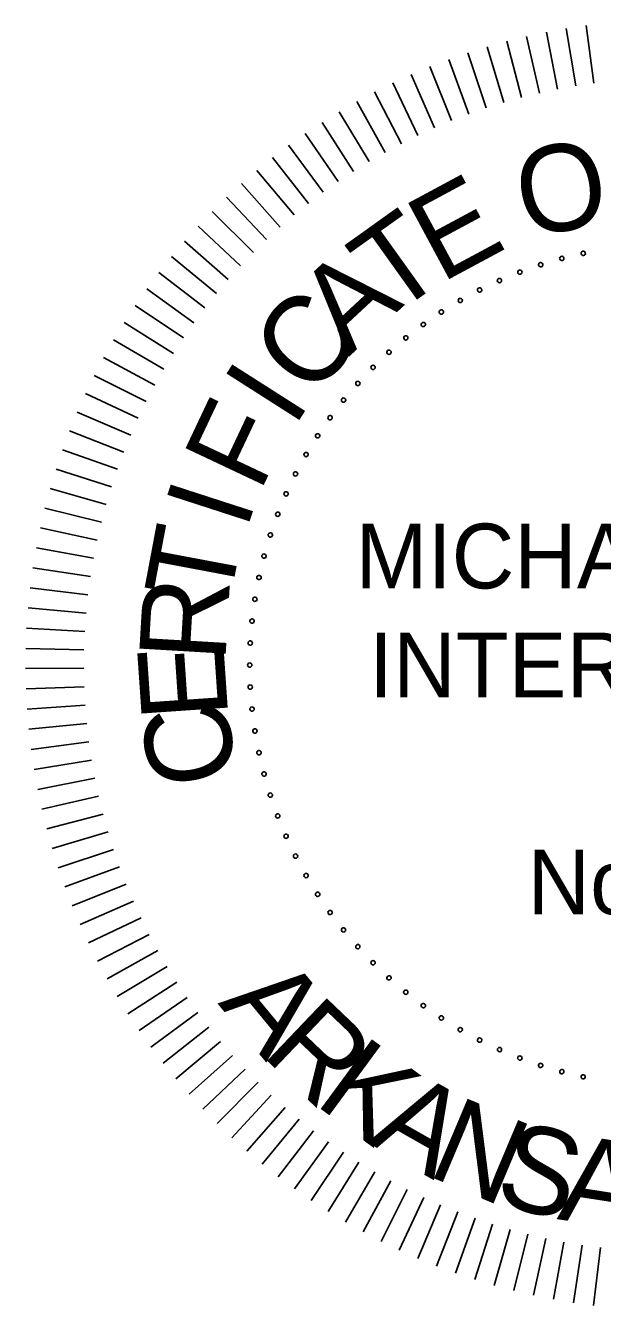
# Model space of a CAD drawing. Extents: x 166 to 3426, y 71 to 2074.
# Drawn here: x 2685.7 to 2797, y 232.1 to 479 of the extents above; entities that cross this region are included whole.
import ezdxf

# ---------------------------------------------------------------- set-up
doc = ezdxf.new("R2010")
doc.units = 0
doc.layers.add('G-ANNO-TEXT', color=7, linetype='Continuous')

msp = doc.modelspace()

# ---------------------------------------------------------------- linework, layer by layer
at = {"layer": 'G-ANNO-TEXT'}
for points in [[(2784.87, 465.99), (2782.36, 476.93)], [(2782.36, 476.93), (2784.87, 465.99)], [(2788.35, 466.73), (2786.19, 477.74)], [(2786.19, 477.74), (2788.35, 466.73)], [(2791.85, 467.36), (2790.03, 478.44)], [(2790.03, 478.44), (2791.85, 467.36)], [(2795.37, 467.88), (2793.9, 479.01)], [(2793.9, 479.01), (2795.37, 467.88)], [(2777.99, 464.19), (2774.8, 474.94)], [(2774.8, 474.94), (2777.99, 464.19)], [(2781.42, 465.14), (2778.57, 476)], [(2778.57, 476), (2781.42, 465.14)], [(2771.24, 461.95), (2767.38, 472.49)], [(2767.38, 472.49), (2771.24, 461.95)], [(2774.6, 463.12), (2771.07, 473.77)], [(2771.07, 473.77), (2774.6, 463.12)], [(2764.64, 459.29), (2760.13, 469.57)], [(2760.13, 469.57), (2764.64, 459.29)], [(2767.92, 460.67), (2763.73, 471.09)], [(2763.73, 471.09), (2767.92, 460.67)], [(2761.41, 457.81), (2756.57, 467.94)], [(2756.57, 467.94), (2761.41, 457.81)], [(2755.09, 454.55), (2749.63, 464.35)], [(2749.63, 464.35), (2755.09, 454.55)], [(2758.22, 456.23), (2753.07, 466.2)], [(2753.07, 466.2), (2758.22, 456.23)], [(2752.01, 452.77), (2746.24, 462.4)], [(2746.24, 462.4), (2752.01, 452.77)], [(2748.99, 450.89), (2742.92, 460.34)], [(2742.92, 460.34), (2748.99, 450.89)], [(2746.03, 448.92), (2739.67, 458.17)], [(2739.67, 458.17), (2746.03, 448.92)], [(2743.13, 446.86), (2736.48, 455.91)], [(2740.3, 444.71), (2733.37, 453.54)], [(2733.37, 453.54), (2740.3, 444.71)], [(2737.53, 442.47), (2730.33, 451.08)], [(2730.33, 451.08), (2737.53, 442.47)], [(2734.84, 440.15), (2727.37, 448.52)], [(2727.37, 448.52), (2734.84, 440.15)], [(2732.22, 437.74), (2724.5, 445.88)], [(2724.5, 445.88), (2732.22, 437.74)], [(2729.68, 435.25), (2721.7, 443.14)], [(2721.7, 443.14), (2729.68, 435.25)], [(2727.22, 432.68), (2719, 440.32)], [(2719, 440.32), (2727.22, 432.68)], [(2724.84, 430.04), (2716.38, 437.41)], [(2716.38, 437.41), (2724.84, 430.04)], [(2722.55, 427.32), (2713.86, 434.43)], [(2713.86, 434.43), (2722.55, 427.32)], [(2720.34, 424.53), (2711.43, 431.36)], [(2711.43, 431.36), (2720.34, 424.53)], [(2718.22, 421.68), (2709.1, 428.22)], [(2709.1, 428.22), (2718.22, 421.68)], [(2716.19, 418.76), (2706.87, 425.01)], [(2706.87, 425.01), (2716.19, 418.76)], [(2714.26, 415.77), (2704.75, 421.73)], [(2704.75, 421.73), (2714.26, 415.77)], [(2712.41, 412.73), (2702.72, 418.39)], [(2702.72, 418.39), (2712.41, 412.73)], [(2710.67, 409.63), (2700.8, 414.98)], [(2700.8, 414.98), (2710.67, 409.63)], [(2709.02, 406.48), (2698.99, 411.52)], [(2698.99, 411.52), (2709.02, 406.48)], [(2707.48, 403.27), (2697.29, 408)], [(2697.29, 408), (2707.48, 403.27)], [(2706.03, 400.02), (2695.71, 404.42)], [(2695.71, 404.42), (2706.03, 400.02)], [(2704.69, 396.73), (2694.23, 400.8)], [(2694.23, 400.8), (2704.69, 396.73)], [(2703.45, 393.4), (2692.87, 397.14)], [(2692.87, 397.14), (2703.45, 393.4)], [(2702.32, 390.03), (2691.62, 393.43)], [(2691.62, 393.43), (2702.32, 390.03)], [(2701.29, 386.62), (2690.49, 389.69)], [(2690.49, 389.69), (2701.29, 386.62)], [(2700.37, 383.18), (2689.48, 385.91)], [(2689.48, 385.91), (2700.37, 383.18)], [(2699.56, 379.72), (2688.59, 382.11)], [(2688.59, 382.11), (2699.56, 379.72)], [(2698.86, 376.23), (2687.82, 378.28)], [(2687.82, 378.28), (2698.86, 376.23)], [(2698.26, 372.73), (2687.17, 374.42)], [(2687.17, 374.42), (2698.26, 372.73)], [(2697.78, 369.2), (2686.64, 370.55)], [(2686.64, 370.55), (2697.78, 369.2)], [(2697.41, 365.67), (2686.23, 366.66)], [(2686.23, 366.66), (2697.41, 365.67)], [(2697.15, 362.12), (2685.95, 362.76)], [(2685.95, 362.76), (2697.15, 362.12)], [(2697, 358.57), (2685.79, 358.86)], [(2685.79, 358.86), (2697, 358.57)], [(2696.97, 355.01), (2685.75, 354.95)], [(2685.75, 354.95), (2696.97, 355.01)], [(2697.04, 351.45), (2685.83, 351.04)], [(2685.83, 351.04), (2697.04, 351.45)], [(2697.23, 347.9), (2686.04, 347.13)], [(2686.04, 347.13), (2697.23, 347.9)], [(2697.53, 344.36), (2686.36, 343.24)], [(2686.36, 343.24), (2697.53, 344.36)], [(2697.94, 340.82), (2686.81, 339.36)], [(2686.81, 339.36), (2697.94, 340.82)], [(2698.46, 337.31), (2687.39, 335.49)], [(2687.39, 335.49), (2698.46, 337.31)], [(2699.09, 333.81), (2688.08, 331.64)], [(2688.08, 331.64), (2699.09, 333.81)], [(2699.83, 330.33), (2688.89, 327.82)], [(2688.89, 327.82), (2699.83, 330.33)], [(2700.68, 326.87), (2689.83, 324.02)], [(2689.83, 324.02), (2700.68, 326.87)], [(2701.64, 323.45), (2690.88, 320.26)], [(2690.88, 320.26), (2701.64, 323.45)], [(2702.71, 320.05), (2692.05, 316.53)], [(2692.05, 316.53), (2702.71, 320.05)], [(2703.88, 316.7), (2693.34, 312.83)], [(2693.34, 312.83), (2703.88, 316.7)], [(2705.15, 313.38), (2694.74, 309.19)], [(2694.74, 309.19), (2705.15, 313.38)], [(2706.53, 310.1), (2696.26, 305.58)], [(2696.26, 305.58), (2706.53, 310.1)], [(2708.01, 306.86), (2697.88, 302.03)], [(2697.88, 302.03), (2708.01, 306.86)], [(2709.6, 303.68), (2699.62, 298.53)], [(2699.62, 298.53), (2709.6, 303.68)], [(2711.28, 300.54), (2701.47, 295.08)], [(2701.47, 295.08), (2711.28, 300.54)], [(2713.06, 297.46), (2703.43, 291.7)], [(2703.43, 291.7), (2713.06, 297.46)], [(2714.93, 294.44), (2705.49, 288.38)], [(2705.49, 288.38), (2714.93, 294.44)], [(2716.9, 291.48), (2707.65, 285.12)], [(2707.65, 285.12), (2716.9, 291.48)], [(2718.96, 288.58), (2709.92, 281.94)], [(2709.92, 281.94), (2718.96, 288.58)], [(2721.11, 285.75), (2712.28, 278.82)], [(2712.28, 278.82), (2721.11, 285.75)], [(2723.35, 282.99), (2714.75, 275.78)], [(2714.75, 275.78), (2723.35, 282.99)], [(2725.68, 280.29), (2717.3, 272.83)], [(2717.3, 272.83), (2725.68, 280.29)], [(2728.09, 277.68), (2719.95, 269.95)], [(2719.95, 269.95), (2728.09, 277.68)], [(2730.58, 275.14), (2722.68, 267.16)], [(2722.68, 267.16), (2730.58, 275.14)], [(2733.14, 272.68), (2725.51, 264.45)], [(2725.51, 264.45), (2733.14, 272.68)], [(2728.41, 261.84), (2735.79, 270.3)], [(2735.79, 270.3), (2728.41, 261.84)], [(2731.4, 259.32), (2738.5, 268)], [(2738.5, 268), (2731.4, 259.32)], [(2734.46, 256.89), (2741.29, 265.79)], [(2741.29, 265.79), (2734.46, 256.89)], [(2737.6, 254.56), (2744.15, 263.67)], [(2744.15, 263.67), (2737.6, 254.56)], [(2740.81, 252.33), (2747.07, 261.65)], [(2747.07, 261.65), (2740.81, 252.33)], [(2744.09, 250.2), (2750.05, 259.71)], [(2750.05, 259.71), (2744.09, 250.2)], [(2747.44, 248.18), (2753.1, 257.87)], [(2753.1, 257.87), (2747.44, 248.18)], [(2750.84, 246.26), (2756.2, 256.12)], [(2756.2, 256.12), (2750.84, 246.26)], [(2754.31, 244.45), (2759.35, 254.48)], [(2759.35, 254.48), (2754.31, 244.45)], [(2757.83, 242.75), (2762.55, 252.93)], [(2762.55, 252.93), (2757.83, 242.75)], [(2761.4, 241.16), (2765.8, 251.48)], [(2765.8, 251.48), (2761.4, 241.16)], [(2765.02, 239.68), (2769.09, 250.14)], [(2769.09, 250.14), (2765.02, 239.68)], [(2768.69, 238.32), (2772.43, 248.9)], [(2772.43, 248.9), (2768.69, 238.32)], [(2772.39, 237.08), (2775.8, 247.77)], [(2775.8, 247.77), (2772.39, 237.08)], [(2776.13, 235.95), (2779.21, 246.74)], [(2779.21, 246.74), (2776.13, 235.95)], [(2779.91, 234.94), (2782.64, 245.82)], [(2782.64, 245.82), (2779.91, 234.94)], [(2783.72, 234.05), (2786.1, 245.01)], [(2786.1, 245.01), (2783.72, 234.05)], [(2787.55, 233.27), (2789.59, 244.31)], [(2789.59, 244.31), (2787.55, 233.27)], [(2791.4, 232.62), (2793.1, 243.72)], [(2793.1, 243.72), (2791.4, 232.62)], [(2795.28, 232.09), (2796.62, 243.24)], [(2796.62, 243.24), (2795.28, 232.09)]]:
    msp.add_lwpolyline(points, dxfattribs=at)
for centre, start, end in [((2793.3, 435.08), 12, 192), ((2793.3, 435.08), 192, 12), ((2785.09, 432.88), 18, 198), ((2785.09, 432.88), 198, 18), ((2789.17, 434.09), 15, 195), ((2789.17, 434.09), 195, 15), ((2777.15, 429.83), 24, 204), ((2777.15, 429.83), 204, 24), ((2781.08, 431.46), 21, 201), ((2781.08, 431.46), 201, 21), ((2773.32, 428), 27, 207), ((2773.32, 428), 207, 27), ((2769.58, 425.97), 30, 210), ((2769.58, 425.97), 210, 30), ((2765.95, 423.75), 33, 213), ((2765.95, 423.75), 213, 33), ((2762.45, 421.34), 36, 216), ((2762.45, 421.34), 216, 36), ((2759.08, 418.76), 39, 219), ((2759.08, 418.76), 219, 39), ((2755.84, 415.99), 42, 222), ((2755.84, 415.99), 222, 42), ((2752.76, 413.07), 45, 225), ((2752.76, 413.07), 225, 45), ((2749.83, 409.98), 48, 228), ((2749.83, 409.98), 228, 48), ((2747.07, 406.75), 51, 231), ((2747.07, 406.75), 231, 51), ((2744.48, 403.38), 54, 234), ((2744.48, 403.38), 234, 54), ((2742.07, 399.87), 57, 237), ((2742.07, 399.87), 237, 57), ((2739.85, 396.25), 60, 240), ((2739.85, 396.25), 240, 60), ((2737.82, 392.51), 63, 243), ((2737.82, 392.51), 243, 63), ((2735.99, 388.67), 66, 246), ((2735.99, 388.67), 246, 66), ((2734.37, 384.74), 69, 249), ((2734.37, 384.74), 249, 69), ((2732.95, 380.74), 72, 252), ((2732.95, 380.74), 252, 72), ((2731.74, 376.66), 75, 255), ((2731.74, 376.66), 255, 75), ((2730.75, 372.53), 78, 258), ((2730.75, 372.53), 258, 78), ((2729.97, 368.34), 81, 261), ((2729.97, 368.34), 261, 81), ((2729.42, 364.13), 84, 264), ((2729.42, 364.13), 264, 84), ((2729.08, 359.89), 87, 267), ((2729.08, 359.89), 267, 87), ((2728.97, 355.64), 90, 270), ((2728.97, 355.64), 270, 90), ((2729.08, 351.39), 93, 273), ((2729.08, 351.39), 273, 93), ((2729.42, 347.15), 96, 276), ((2729.42, 347.15), 276, 96), ((2729.97, 342.93), 99, 279), ((2729.97, 342.93), 279, 99), ((2730.75, 338.75), 102, 282), ((2730.75, 338.75), 282, 102), ((2731.74, 334.62), 105, 285), ((2731.74, 334.62), 285, 105), ((2732.95, 330.54), 108, 288), ((2732.95, 330.54), 288, 108), ((2734.37, 326.53), 111, 291), ((2734.37, 326.53), 291, 111), ((2735.99, 322.61), 114, 294), ((2735.99, 322.61), 294, 114), ((2737.82, 318.77), 117, 297), ((2737.82, 318.77), 297, 117), ((2739.85, 315.03), 120, 300), ((2739.85, 315.03), 300, 120), ((2742.07, 311.41), 123, 303), ((2742.07, 311.41), 303, 123), ((2744.48, 307.9), 126, 306), ((2744.48, 307.9), 306, 126), ((2747.07, 304.53), 129, 309), ((2747.07, 304.53), 309, 129), ((2749.83, 301.3), 132, 312), ((2749.83, 301.3), 312, 132), ((2752.76, 298.21), 135, 315), ((2752.76, 298.21), 315, 135), ((2755.84, 295.29), 138, 318), ((2755.84, 295.29), 318, 138), ((2759.08, 292.52), 141, 321), ((2759.08, 292.52), 321, 141), ((2762.45, 289.94), 144, 324), ((2762.45, 289.94), 324, 144), ((2765.95, 287.53), 147, 327), ((2765.95, 287.53), 327, 147), ((2769.58, 285.31), 150, 330), ((2769.58, 285.31), 330, 150), ((2773.32, 283.28), 153, 333), ((2773.32, 283.28), 333, 153), ((2777.15, 281.45), 156, 336), ((2777.15, 281.45), 336, 156), ((2781.08, 279.82), 159, 339), ((2781.08, 279.82), 339, 159), ((2785.09, 278.4), 162, 342), ((2785.09, 278.4), 342, 162), ((2789.17, 277.19), 165, 345), ((2789.17, 277.19), 345, 165), ((2793.3, 276.2), 348, 168), ((2793.3, 276.2), 168, 348)]:
    msp.add_arc(centre, 0.417, start, end, dxfattribs=at)

# ---------------------------------------------------------------- texts
for s, rotation, p in [('O', 10.7295, (2782.03, 437.96)), ('E', 28.279, (2765.84, 429.23)), ('T', 35.5725, (2756.54, 422.78)), ('A', 42.8659, (2748.07, 415.08)), ('C', 50.1594, (2741.06, 406.75)), ('I', 57.4529, (2737.44, 401.18)), ('F', 64.7464, (2730.9, 388.71)), ('I', 72.0398, (2728.32, 381.39)), ('T', 79.3333, (2725, 367.03)), ('R', 86.6268, (2724.24, 356.01)), ('E', 93.9203, (2724.85, 345.6)), ('C', 101.2137, (2726.99, 334)), ('A', 309.5859, (2722.72, 290.37)), ('R', 316.3356, (2731, 280.55)), ('K', 323.6428, (2741.19, 271.09)), ('A', 330.3925, (2751.61, 263.56)), ('N', 337.1422, (2762.84, 257.32)), ('S', 344.4494, (2775.73, 252.09)), ('A', 351.1991, (2788.13, 248.76))]:
    msp.add_text(s, height=16.67, rotation=rotation, dxfattribs=at).set_placement(p)
for s, height, p in [('MICHAEL BAKER', 12.5016, (2749.36, 370.42)), (' INTERNATIONAL', 12.5016, (2747.35, 349.39)), (' No. 1126', 12.502, (2777.92, 307.54))]:
    msp.add_text(s, height=height, dxfattribs=at).set_placement(p)

doc.saveas('drawing.dxf')
